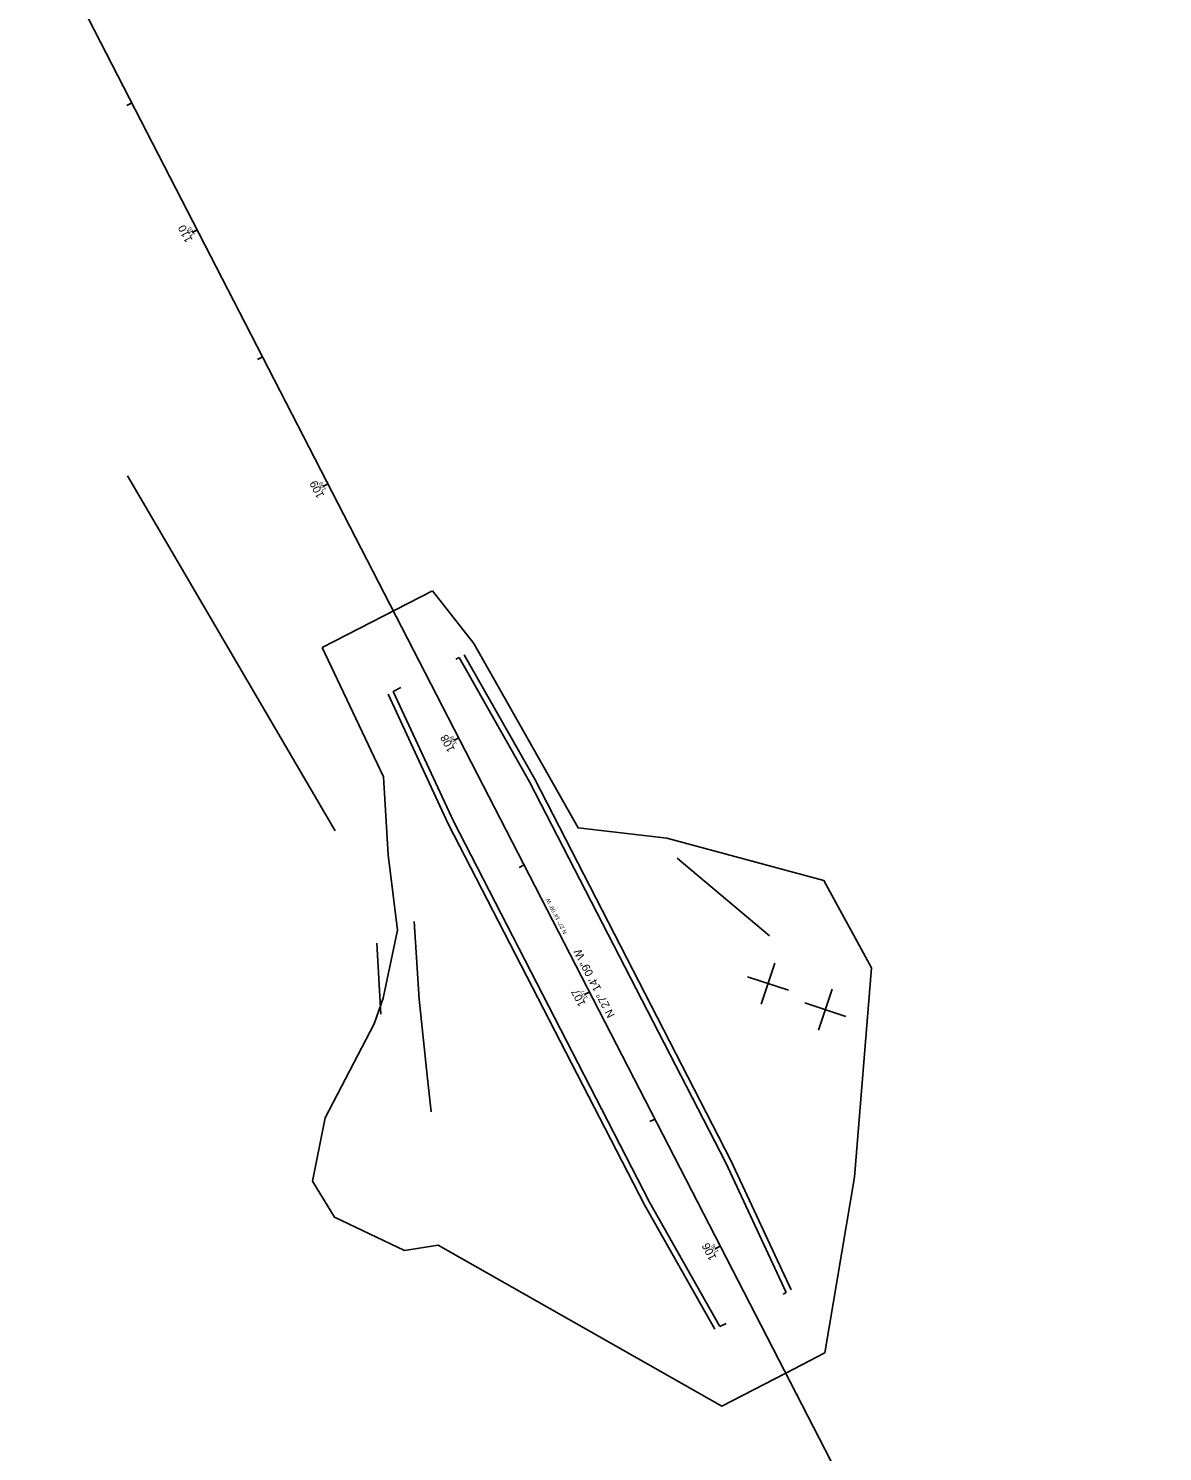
# Model space of a CAD drawing. Extents: x 1715640 to 1716553, y 394047 to 395910.
# Drawn here: x 1715852.5 to 1716249.5, y 394914.2 to 395412.2 of the extents above; entities that cross this region are included whole.
import ezdxf

# ---------------------------------------------------------------- set-up
doc = ezdxf.new("R2010")
doc.units = 0
for name, color, linetype in [('DR_P_Ditch', 7, 'Continuous'), ('DT_P_Graded_Shoulder', 7, 'Continuous'), ('GE_P_CL_10', 7, 'Continuous'), ('GE_P_CL_20', 7, 'Continuous'), ('PV_P_Shoulder', 7, 'Continuous'), ('RD_X_Fence', 7, 'Continuous'), ('RW_P_Const_Limits', 7, 'Continuous'), ('UT_X_Water', 7, 'Continuous'), ('VG_P_Cells', 7, 'Continuous')]:
    doc.layers.add(name, color=color, linetype=linetype)

msp = doc.modelspace()

# ---------------------------------------------------------------- linework, layer by layer
at = {"layer": 'DR_P_Ditch'}
for p, q in [((1716079.55, 395121.82), (1716111.88, 395094.71)), ((1715987.58, 395099.69), (1715989.32, 395072.47)), ((1715989.32, 395072.47), (1715992.12, 395045.79)), ((1715992.12, 395045.79), (1715993.46, 395033.13))]:
    msp.add_line(p, q, dxfattribs=at)
at = {"layer": 'DT_P_Graded_Shoulder'}
for p, q in [((1716029.71, 395149.49), (1716005.05, 395193.04)), ((1715978.38, 395179.31), (1715999.48, 395133.93)), ((1716098.36, 395016.12), (1716029.71, 395149.49)), ((1716068.13, 395000.56), (1715999.48, 395133.93)), ((1716119.47, 394970.75), (1716098.36, 395016.12)), ((1716092.79, 394957.02), (1716068.13, 395000.56))]:
    msp.add_line(p, q, dxfattribs=at)
at = {"layer": 'GE_P_CL_10'}
for p, q in [((1716249.46, 394685.42), (1715852.54, 395456.56)), ((1715888.74, 395386.22), (1715887.85, 395385.77)), ((1715911.63, 395341.77), (1715910.74, 395341.31)), ((1715934.51, 395297.31), (1715933.62, 395296.85)), ((1715957.39, 395252.86), (1715956.5, 395252.4)), ((1715980.27, 395208.4), (1715979.38, 395207.94)), ((1716003.16, 395163.94), (1716002.27, 395163.48)), ((1716026.04, 395119.49), (1716025.15, 395119.03)), ((1716048.92, 395075.03), (1716048.03, 395074.57)), ((1716071.8, 395030.57), (1716070.92, 395030.11)), ((1716094.69, 394986.12), (1716093.8, 394985.66)), ((1716117.57, 394941.66), (1716116.68, 394941.2))]:
    msp.add_line(p, q, dxfattribs=at)
at = {"layer": 'GE_P_CL_20'}
for p, q in [((1716249.46, 394685.42), (1715852.54, 395456.56)), ((1715888.74, 395386.22), (1715886.96, 395385.31)), ((1715911.63, 395341.77), (1715909.85, 395340.85)), ((1715934.51, 395297.31), (1715932.73, 395296.4)), ((1715957.39, 395252.86), (1715955.61, 395251.94)), ((1715980.27, 395208.4), (1715978.5, 395207.48)), ((1716003.16, 395163.94), (1716001.38, 395163.03)), ((1716026.04, 395119.49), (1716024.26, 395118.57)), ((1716048.92, 395075.03), (1716047.14, 395074.11)), ((1716071.8, 395030.57), (1716070.03, 395029.66)), ((1716094.69, 394986.12), (1716092.91, 394985.2)), ((1716117.57, 394941.66), (1716115.79, 394940.74))]:
    msp.add_line(p, q, dxfattribs=at)
at = {"layer": 'PV_P_Shoulder'}
for p, q in [((1716002.11, 395191.52), (1716003.27, 395192.12)), ((1716003.27, 395192.12), (1716027.93, 395148.58)), ((1715982.86, 395181.61), (1715980.16, 395180.22)), ((1716001.26, 395134.85), (1715980.16, 395180.22)), ((1716096.58, 395015.21), (1716027.93, 395148.58)), ((1716069.91, 395001.48), (1716001.26, 395134.85)), ((1716096.58, 395015.21), (1716117.69, 394969.84)), ((1716094.57, 394957.94), (1716069.91, 395001.48)), ((1716117.69, 394969.84), (1716116.66, 394969.31)), ((1716094.57, 394957.94), (1716096.7, 394959.03))]:
    msp.add_line(p, q, dxfattribs=at)
at = {"layer": 'RD_X_Fence'}
msp.add_line((1715975.92, 395067.23), (1715974.49, 395092.17), dxfattribs=at)
at = {"layer": 'RW_P_Const_Limits'}
for p, q in [((1715993.99, 395215.46), (1715955.37, 395195.58)), ((1716131.3, 394948.73), (1716117.57, 394941.66))]:
    msp.add_line(p, q, dxfattribs=at)
for points in [[(1716131.3, 394948.73), (1716141.64, 395010.28), (1716147.61, 395083.46), (1716130.96, 395114.02), (1716075.92, 395128.83), (1716044.88, 395132.47), (1716008.44, 395197.03), (1715993.99, 395215.46)], [(1716117.57, 394941.66), (1716095.18, 394930.14), (1715995.91, 394986.48), (1715984.19, 394984.61), (1715959.63, 394996.27), (1715951.97, 395008.78), (1715956.44, 395030.99), (1715973.58, 395063.89), (1715976.74, 395072.93), (1715981.72, 395096.67), (1715978.41, 395123.09), (1715976.81, 395150.38), (1715955.37, 395195.58)]]:
    msp.add_lwpolyline(points, dxfattribs=at)
at = {"layer": 'UT_X_Water'}
msp.add_line((1715959.86, 395131.46), (1715887.23, 395255.65), dxfattribs=at)
at = {"layer": 'VG_P_Cells'}
for p, q in [((1716109.04, 395070.83), (1716113.78, 395085.18)), ((1716104.23, 395080.38), (1716118.59, 395075.63)), ((1716111.41, 395078.01), (1716111.41, 395078.01)), ((1716129.07, 395061.69), (1716133.81, 395076.04)), ((1716124.26, 395071.24), (1716138.62, 395066.49)), ((1716131.44, 395068.86), (1716131.44, 395068.86))]:
    msp.add_line(p, q, dxfattribs=at)

# ---------------------------------------------------------------- texts
at = {"layer": 'GE_P_CL_10'}
for s, p in [('110', (1715910.85, 395340)), ('109', (1715956.76, 395250.81)), ('108', (1716002.51, 395161.91)), ('N 27%%d 14\' 09" W', (1716041.04, 395095.79)), ('107', (1716048.31, 395072.95)), ('106', (1716094.06, 394984.06))]:
    msp.add_text(s, height=1.4, rotation=117.2357, dxfattribs=at).set_placement(p)
at = {"layer": 'GE_P_CL_20'}
for s, p in [('110', (1715910.07, 395338.23)), ('109', (1715956.13, 395248.76)), ('108', (1716001.87, 395159.88)), ('N 27%%d 14\' 09" W', (1716057.84, 395066.89)), ('107', (1716047.69, 395070.86)), ('106', (1716093.43, 394982))]:
    msp.add_text(s, height=2.8, rotation=117.2357, dxfattribs=at).set_placement(p)

doc.saveas('drawing.dxf')
